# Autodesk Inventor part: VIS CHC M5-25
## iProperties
Created: 2004-11
Part Number: VIS CHC M5-25
Document SubType Name: Modeling
Designer: Bruno
Manufacturer: Standard
Standards Organization: Custom
Author: Bruno
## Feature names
1. Base1
